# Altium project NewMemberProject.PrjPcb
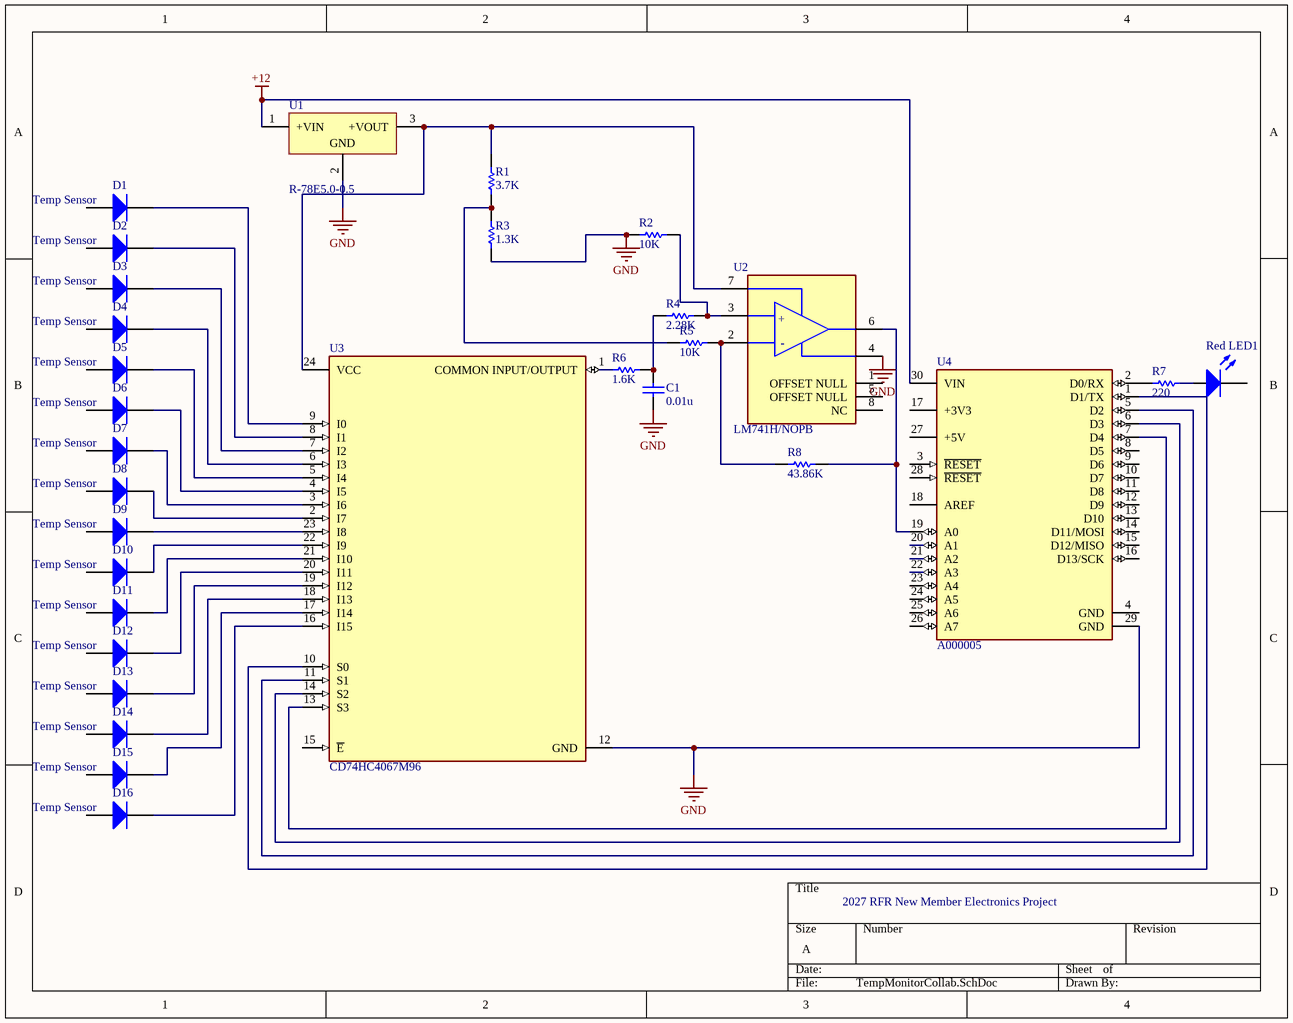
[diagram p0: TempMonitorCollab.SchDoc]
1 sheet, 30 parts. Net scope: global (net labels, ports and power ports of the same name join across sheets).

## Sheet TempMonitorCollab.SchDoc
size A; SheetNumber: 1; SheetTotal: 1

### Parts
C1  value 0.01u  (hidden comment: Capacitor)
D1  Diode  (value not drawn)
D2  Diode  (value not drawn)
D3  Diode  (value not drawn)
D4  Diode  (value not drawn)
D5  Diode  (value not drawn)
D6  Diode  (value not drawn)
D7  Diode  (value not drawn)
D8  Diode  (value not drawn)
D9  Diode  (value not drawn)
D10  Diode  (value not drawn)
D11  Diode  (value not drawn)
D12  Diode  (value not drawn)
D13  Diode  (value not drawn)
D14  Diode  (value not drawn)
D15  Diode  (value not drawn)
D16  Diode  (value not drawn)
R1  value 3.7K  (hidden comment: Resistor)
R2  value 10K  (hidden comment: Resistor)
R3  value 1.3K  (hidden comment: Resistor)
R4  value 2.28K  (hidden comment: Resistor)
R5  value 10K  (hidden comment: Resistor)
R6  value 1.6K  (hidden comment: Resistor)
R7  value 220  (hidden comment: Resistor)
R8  value 43.86K  (hidden comment: Resistor)
Red_LED1  Light-Emitting Diode  (value not drawn)
U1  R-78E5.0-0.5  [REPO-R-78E-0.5-3_V]
U2  LM741H/NOPB  [FP-LMC0008A-MFG]
U3  CD74HC4067M96  [FP-DW0024A-MFG]
U4  A000005  [FP-A000005-MFG]

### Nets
+12: U1.1(+VIN) U4.30(VIN)
GND: C1.1 R2.1 R3.1 U1.2(GND) U2.4(V-) U3.12(GND) U4.29(GND)
NetC1_2: C1.2 R4.1 R6.2
NetD1_2: D1.2(K) U3.9(I0)
NetD2_2: D2.2(K) U3.8(I1)
NetD3_2: D3.2(K) U3.7(I2)
NetD4_2: D4.2(K) U3.6(I3)
NetD5_2: D5.2(K) U3.5(I4)
NetD6_2: D6.2(K) U3.4(I5)
NetD7_2: D7.2(K) U3.3(I6)
NetD8_2: D8.2(K) U3.2(I7)
NetD9_2: D9.2(K) U3.23(I8)
NetD10_2: D10.2(K) U3.22(I9)
NetD11_2: D11.2(K) U3.21(I10)
NetD12_2: D12.2(K) U3.20(I11)
NetD13_2: D13.2(K) U3.19(I12)
NetD14_2: D14.2(K) U3.18(I13)
NetD15_2: D15.2(K) U3.17(I14)
NetD16_2: D16.2(K) U3.16(I15)
NetR1_1: R1.1 R3.2 R5.1
NetR1_2: R1.2 U1.3(+VOUT) U2.7(V+) U3.24(VCC)
NetR2_2: R2.2 R4.2 U2.3(NON-INVERTING_INPUT)
NetR5_2: R5.2 R8.1 U2.2(INVERTING_INPUT)
NetR6_1: R6.1 U3.1(COMMON_INPUT/OUTPUT)
NetR7_1: R7.1 U4.2(D0/RX)
NetR7_2: R7.2 Red_LED1.1(A)
NetR8_2: R8.2 U2.6(OUTPUT) U4.19(A0)
NetU3_10: U3.10(S0) U4.1(D1/TX)
NetU3_11: U3.11(S1) U4.5(D2)
NetU3_13: U3.13(S3) U4.7(D4)
NetU3_14: U3.14(S2) U4.6(D3)

Not connected (* = marked no-connect by the designer): D1 1(A); D2 1(A); D3 1(A); D4 1(A); D5 1(A); D6 1(A); D7 1(A); D8 1(A); D9 1(A); D10 1(A); D11 1(A); D12 1(A); D13 1(A); D14 1(A); D15 1(A); D16 1(A); Red_LED1 2(K); U2 1(OFFSET_NULL) 5(OFFSET_NULL) 8(NC); U3 15(~{E}); U4 3(~{RESET}) 4(GND) 8(D5) 9(D6) 10(D7) 11(D8) 12(D9) 13(D10) 14(D11/MOSI) 15(D12/MISO) 16(D13/SCK) 17(+3V3) 18(AREF) 20(A1) 21(A2) 22(A3) 23(A4) 24(A5) 25(A6) 26(A7) 27(+5V) 28(~{RESET})

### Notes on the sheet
- (near D1) Temp Sensor
- (near D2) Temp Sensor
- (near D3) Temp Sensor
- (near D4) Temp Sensor
- (near D5) Temp Sensor
- (near D6) Temp Sensor
- (near D7) Temp Sensor
- (near D8) Temp Sensor
- (near D9) Temp Sensor
- (near D10) Temp Sensor
- (near D11) Temp Sensor
- (near D12) Temp Sensor
- (near D13) Temp Sensor
- (near D14) Temp Sensor
- (near D15) Temp Sensor
- (near D16) Temp Sensor
- 2027 RFR New Member Electronics Project

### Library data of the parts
C1 = Capacitor: SimulationGenericComponent: True
D1-D16 = Diode: AF: 1; BV: 0; BV_MAX: 1e99; EG: 1.11; FC: 0.5; IBV: 0.001; ISR: 1e-14; MJSW: 0.33; NTUN: 30; TNOM: 27; XTI: 3; SimulationGenericComponent: True
R1-R8 = Resistor: TC1: 0; SimulationGenericComponent: True
Red_LED1 = LED: AF: 1; BV: 0; BV_MAX: 1e99; EG: 1.11; FC: 0.5; IBV: 0.001; IS: 1e-14; MJSW: 0.33; NTUN: 30; TNOM: 27; XTI: 3; SimulationGenericComponent: True
U1 = CMP-2000-06922-2: DC/DC-Converter, 5 V Single Output, 500 mA, -40 to 85 degC, 3-Pin THD, RoHS, Tube; Manufacturer: Recom Power; Efficiency: 92%; Number of Outputs: 1; Current - Output (Max): 500mA; VIN Min: 7V; Package Version: Rev. 0; VIN Max: 28V; VOUT: 5V
U2 = CMP-04895-000268-1: IC OPAMP GP 1 CIRCUIT TO99-8; Output Current per Channel: 25mA; Voltage Gain: 106.02dB; Input Offset Voltage (Vos): 1mV; Max Dual Supply Voltage: 22V; Min Dual Supply Voltage: 5V; Slew Rate: 0.5V/µs; Amplifier Type: GENERAL PURPOSE; Power Dissipation: 500mW; Gain Bandwidth Product: 1.5MHz; Input Bias Current: 80nA; Supply Current: 1.7mA; Common Mode Rejection Ratio: 70dB; Number of Elements: 1; Power Supply Rejection Ratio (PSRR): 77dB
U3 = CMP-04901-000007-1: IC MUX/DEMUX 1X16 24SOIC; Manufacturer: Texas Instruments; Standoff Height: 0.1mm; Logic Function Desc: Non-Inverting; Max Supply Voltage: 6V; Number Of Inputs: 16; Quiescent Current: 8uA; Number Of Circuits: 1; Propagation Delay: 6ns; Max Junction Temp: +150°C; Min Supply Voltage: 2V
U4 = CMP-189986-000002-1: ARDUINO NANO ATMEGA328 EVAL BRD; Number of Bits: 8; Evaluation Kit: Yes; Operating Supply Voltage: 12V; Interface: I2C; Data Bus Width: 8b; Core Architecture: AVR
